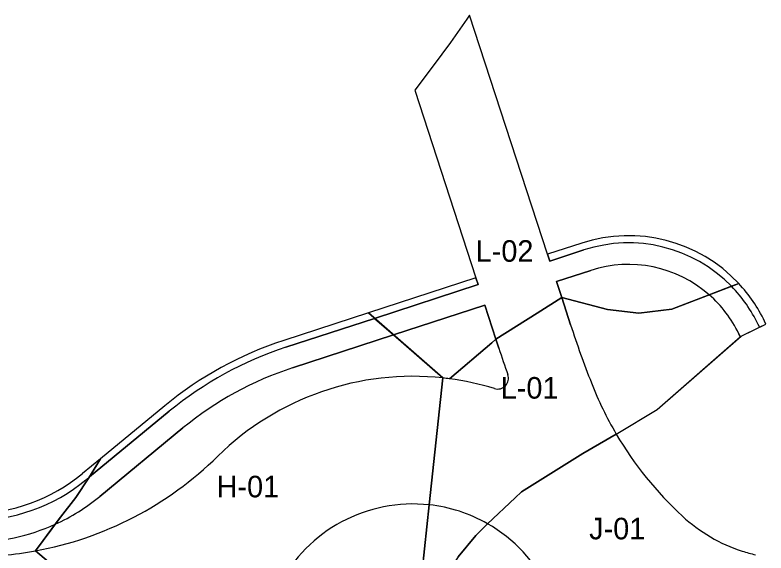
# Model space of a CAD drawing. Extents: x 5196716 to 5200291, y 3709146 to 3713154.
# Drawn here: x 5197340.6 to 5197549.6, y 3709372.1 to 3709521.7 of the extents above; entities that cross this region are included whole.
import ezdxf

# ---------------------------------------------------------------- set-up
doc = ezdxf.new("R2010")
doc.units = 0
for name, color, linetype in [('Drainage-Area', 7, 'Continuous'), ('dsnTextNote', 7, 'Continuous'), ('Level 1', 7, 'Continuous'), ('Level 2', 7, 'Continuous'), ('Level 4', 7, 'Continuous')]:
    doc.layers.add(name, color=color, linetype=linetype)

msp = doc.modelspace()

# ---------------------------------------------------------------- linework, layer by layer
at = {"layer": 'Drainage-Area'}
for points in [[(5197346.24, 3709372.65), (5197348.41, 3709375.52), (5197353.21, 3709382.02), (5197357.53, 3709387.5), (5197361.12, 3709392.93), (5197364.33, 3709398.3)], [(5197366.96, 3709358.52), (5197357.83, 3709363.71), (5197351.66, 3709368.11), (5197346.24, 3709372.65)]]:
    msp.add_lwpolyline(points, dxfattribs=at)
at = {"layer": 'Level 1'}
for p, q in [((5197488.79, 3709455.14), (5197467.07, 3709521.68)), ((5197451.81, 3709500.78), (5197468.83, 3709448.63)), ((5197498.3, 3709458.24), (5197488.79, 3709455.14)), ((5197498.3, 3709458.24), (5197488.79, 3709455.14)), ((5197468.83, 3709448.63), (5197438.91, 3709438.86)), ((5197438.91, 3709438.86), (5197415.36, 3709431.18)), ((5197459.67, 3709420.75), (5197438.91, 3709438.86)), ((5197438.91, 3709438.86), (5197459.67, 3709420.75)), ((5197542.62, 3709432.37), (5197549.57, 3709435.71)), ((5197549.57, 3709435.71), (5197549.18, 3709436.51)), ((5197549.57, 3709435.71), (5197549.18, 3709436.51)), ((5197519.27, 3709412.01), (5197542.62, 3709432.37)), ((5197455.86, 3709385.45), (5197459.67, 3709420.75)), ((5197459.67, 3709420.75), (5197455.86, 3709385.45)), ((5197382.24, 3709413.02), (5197364.33, 3709398.3)), ((5197507.89, 3709405.15), (5197519.27, 3709412.01)), ((5197498.6, 3709399.71), (5197507.89, 3709405.15)), ((5197498.6, 3709399.71), (5197507.89, 3709405.15)), ((5197507.89, 3709405.15), (5197498.6, 3709399.71)), ((5197481.5, 3709389.08), (5197498.6, 3709399.71)), ((5197498.6, 3709399.71), (5197481.5, 3709389.08)), ((5197481.5, 3709389.08), (5197498.6, 3709399.71)), ((5197498.6, 3709399.71), (5197481.5, 3709389.08)), ((5197364.33, 3709398.3), (5197359.35, 3709394.21)), ((5197479.8, 3709387.44), (5197481.5, 3709389.08)), ((5197481.5, 3709389.08), (5197479.8, 3709387.44)), ((5197479.8, 3709387.44), (5197481.5, 3709389.08)), ((5197481.5, 3709389.08), (5197479.8, 3709387.44)), ((5197472.07, 3709380.22), (5197479.8, 3709387.44)), ((5197479.8, 3709387.44), (5197472.07, 3709380.22)), ((5197472.07, 3709380.22), (5197479.8, 3709387.44)), ((5197479.8, 3709387.44), (5197472.07, 3709380.22)), ((5197451.32, 3709343.7), (5197455.86, 3709385.45)), ((5197455.86, 3709385.45), (5197451.32, 3709343.7))]:
    msp.add_line(p, q, dxfattribs=at)
for points in [[(5197467.07, 3709521.68), (5197466.31, 3709520.55), (5197461.73, 3709514.05), (5197456.99, 3709507.53), (5197451.81, 3709500.78)], [(5197541.97, 3709447.04), (5197523.39, 3709439.87), (5197514.18, 3709438.81), (5197505.42, 3709439.75), (5197492.72, 3709443.11)], [(5197492.72, 3709443.11), (5197505.42, 3709439.75), (5197514.18, 3709438.81), (5197523.39, 3709439.87), (5197541.97, 3709447.04)], [(5197492.72, 3709443.11), (5197485.88, 3709438.79), (5197474.4, 3709431.54)], [(5197474.4, 3709431.54), (5197485.88, 3709438.79), (5197492.72, 3709443.11)], [(5197474.4, 3709431.54), (5197473.26, 3709430.56), (5197461.53, 3709420.53)], [(5197461.53, 3709420.53), (5197473.26, 3709430.56), (5197474.4, 3709431.54)], [(5197346.24, 3709372.65), (5197348.41, 3709375.52), (5197353.21, 3709382.02), (5197357.53, 3709387.5), (5197361.12, 3709392.93), (5197364.33, 3709398.3)], [(5197364.33, 3709398.3), (5197361.12, 3709392.93), (5197357.53, 3709387.5), (5197353.21, 3709382.02), (5197348.41, 3709375.52), (5197346.24, 3709372.65)], [(5197472.07, 3709380.22), (5197468.83, 3709376.97), (5197463.95, 3709371), (5197459.45, 3709364.51), (5197455.96, 3709357.22), (5197452.99, 3709349.55), (5197451.32, 3709343.7)], [(5197463.95, 3709371), (5197468.83, 3709376.97), (5197472.07, 3709380.22)], [(5197472.07, 3709380.22), (5197468.83, 3709376.97), (5197463.95, 3709371)], [(5197366.96, 3709358.52), (5197357.83, 3709363.71), (5197351.66, 3709368.11), (5197346.24, 3709372.65)], [(5197346.24, 3709372.65), (5197351.66, 3709368.11), (5197357.83, 3709363.71), (5197366.96, 3709358.52)]]:
    msp.add_lwpolyline(points, dxfattribs=at)
for centre, radius, start, end in [((5197511.33, 3709418.32), 42, 43.1428, 108.0738), ((5197511.33, 3709418.32), 42, 25.6653, 43.1428), ((5197447, 3709334.21), 102, 108.0738, 129.4103), ((5197451.32, 3709343.7), 77.5, 82.4329, 83.8176), ((5197451.32, 3709343.7), 77.5, 82.4329, 83.8176), ((5197594.1, 3709455.83), 100, 210.4479, 227.3156), ((5197328.59, 3709431.06), 48, 269.8345, 309.8603), ((5197556.81, 3709415.4), 45, 227.3156, 252.0632), ((5197556.81, 3709415.4), 45, 252.0632, 256.9145)]:
    msp.add_arc(centre, radius, start, end, dxfattribs=at)
at = {"layer": 'Level 2'}
for p, q in [((5197488.79, 3709455.14), (5197467.07, 3709521.68)), ((5197451.81, 3709500.78), (5197468.83, 3709448.63)), ((5197498.92, 3709456.34), (5197489.41, 3709453.24)), ((5197489.41, 3709453.24), (5197488.79, 3709455.14)), ((5197491.27, 3709447.54), (5197500.78, 3709450.64)), ((5197468.83, 3709448.63), (5197469.45, 3709446.72)), ((5197492.72, 3709443.11), (5197491.27, 3709447.54)), ((5197469.45, 3709446.72), (5197440.66, 3709437.33)), ((5197539.95, 3709446.26), (5197533.76, 3709443.87)), ((5197533.76, 3709443.87), (5197539.95, 3709446.26)), ((5197495.2, 3709435.51), (5197492.72, 3709443.11)), ((5197445.93, 3709432.74), (5197471.31, 3709441.02)), ((5197471.31, 3709441.02), (5197474.4, 3709431.54)), ((5197440.66, 3709437.33), (5197415.98, 3709429.28)), ((5197440.66, 3709437.33), (5197445.93, 3709432.74)), ((5197445.93, 3709432.74), (5197440.66, 3709437.33)), ((5197547.76, 3709434.85), (5197547.38, 3709435.64)), ((5197541.97, 3709433.04), (5197542.39, 3709432.17)), ((5197542.62, 3709432.37), (5197547.76, 3709434.85)), ((5197417.84, 3709423.57), (5197445.93, 3709432.74)), ((5197474.4, 3709431.54), (5197475.23, 3709428.99)), ((5197542.39, 3709432.17), (5197542.62, 3709432.37)), ((5197459.67, 3709420.75), (5197455.86, 3709385.45)), ((5197455.86, 3709385.45), (5197459.67, 3709420.75)), ((5197383.51, 3709411.47), (5197361.29, 3709393.21)), ((5197364.15, 3709387.79), (5197387.32, 3709406.84)), ((5197507.89, 3709405.15), (5197498.6, 3709399.71)), ((5197498.6, 3709399.71), (5197507.89, 3709405.15)), ((5197498.6, 3709399.71), (5197481.5, 3709389.08)), ((5197481.5, 3709389.08), (5197498.6, 3709399.71)), ((5197361.29, 3709393.21), (5197360.34, 3709392.42)), ((5197361.29, 3709393.21), (5197361.12, 3709392.93)), ((5197361.12, 3709392.93), (5197361.29, 3709393.21)), ((5197361.12, 3709392.93), (5197357.53, 3709387.5)), ((5197357.53, 3709387.5), (5197361.12, 3709392.93)), ((5197481.5, 3709389.08), (5197479.8, 3709387.44)), ((5197479.8, 3709387.44), (5197481.5, 3709389.08)), ((5197357.53, 3709387.5), (5197353.21, 3709382.02)), ((5197353.21, 3709382.02), (5197357.53, 3709387.5)), ((5197479.8, 3709387.44), (5197472.07, 3709380.22)), ((5197472.07, 3709380.22), (5197479.8, 3709387.44)), ((5197353.21, 3709382.02), (5197351.78, 3709380.08)), ((5197351.78, 3709380.08), (5197353.21, 3709382.02)), ((5197351.66, 3709368.11), (5197346.24, 3709372.65))]:
    msp.add_line(p, q, dxfattribs=at)
for points in [[(5197467.07, 3709521.68), (5197466.31, 3709520.55), (5197461.73, 3709514.05), (5197456.99, 3709507.53), (5197451.81, 3709500.78)], [(5197492.72, 3709443.11), (5197485.88, 3709438.79), (5197474.4, 3709431.54)], [(5197474.4, 3709431.54), (5197485.88, 3709438.79), (5197492.72, 3709443.11)], [(5197346.24, 3709372.65), (5197351.66, 3709368.11), (5197357.83, 3709363.71), (5197366.96, 3709358.52)]]:
    msp.add_lwpolyline(points, dxfattribs=at)
for centre, radius, start, end in [((5197511.33, 3709418.32), 40, 44.3081, 108.0738), ((5197511.33, 3709418.32), 34, 48.7225, 108.0738), ((5197511.33, 3709418.32), 40, 25.6653, 44.3081), ((5197511.33, 3709418.32), 34, 25.6653, 48.7225), ((5197778.02, 3709527.81), 297.5, 198.0738, 201.3741), ((5197447, 3709334.21), 100, 108.0738, 129.4106), ((5197778.02, 3709527.81), 318.5, 198.0738, 199.4651), ((5197447, 3709334.21), 94, 108.0738, 129.4106), ((5197451.32, 3709343.7), 77.5, 83.8176, 134.4832), ((5197451.32, 3709343.7), 77.5, 82.4329, 83.8176), ((5197451.32, 3709343.7), 77.5, 72.9739, 82.4329), ((5197474.89, 3709420.67), 3, 252.9739, 19.4651), ((5197594.1, 3709455.83), 100, 201.3741, 210.4479), ((5197594.1, 3709455.83), 100, 210.4479, 227.3156), ((5197328.7, 3709468.56), 97.5, 280.3656, 314.4832), ((5197328.59, 3709431.06), 50, 269.8345, 309.4106), ((5197328.59, 3709431.06), 56, 294.4582, 309.4106), ((5197451.32, 3709343.7), 42, 83.8009, 152.6258), ((5197451.32, 3709343.7), 42, 60.3941, 83.8011), ((5197556.81, 3709415.4), 45, 227.3156, 252.0632), ((5197328.59, 3709431.06), 56, 269.8345, 294.4582), ((5197451.32, 3709343.7), 42, 25.7605, 60.3941), ((5197328.7, 3709468.56), 97.5, 269.8354, 280.3656), ((5197556.81, 3709415.4), 45, 252.0632, 256.9145)]:
    msp.add_arc(centre, radius, start, end, dxfattribs=at)
at = {"layer": 'Level 4'}
for p, q in [((5197498.3, 3709458.24), (5197488.79, 3709455.14)), ((5197489.41, 3709453.24), (5197498.92, 3709456.34)), ((5197488.79, 3709455.14), (5197489.41, 3709453.24)), ((5197500.78, 3709450.64), (5197491.27, 3709447.54)), ((5197468.83, 3709448.63), (5197438.91, 3709438.86)), ((5197469.45, 3709446.72), (5197468.83, 3709448.63)), ((5197491.27, 3709447.54), (5197492.72, 3709443.11)), ((5197440.66, 3709437.33), (5197469.45, 3709446.72)), ((5197539.95, 3709446.26), (5197541.97, 3709447.04)), ((5197541.97, 3709447.04), (5197539.95, 3709446.26)), ((5197492.72, 3709443.11), (5197505.42, 3709439.75)), ((5197505.42, 3709439.75), (5197492.72, 3709443.11)), ((5197492.72, 3709443.11), (5197495.2, 3709435.51)), ((5197471.31, 3709441.02), (5197445.93, 3709432.74)), ((5197474.4, 3709431.54), (5197471.31, 3709441.02)), ((5197514.18, 3709438.81), (5197505.42, 3709439.75)), ((5197438.91, 3709438.86), (5197415.36, 3709431.18)), ((5197415.98, 3709429.28), (5197440.66, 3709437.33)), ((5197438.91, 3709438.86), (5197440.66, 3709437.33)), ((5197440.66, 3709437.33), (5197438.91, 3709438.86)), ((5197547.38, 3709435.64), (5197547.76, 3709434.85)), ((5197547.76, 3709434.85), (5197549.57, 3709435.71)), ((5197549.57, 3709435.71), (5197549.18, 3709436.51)), ((5197542.39, 3709432.17), (5197541.97, 3709433.04)), ((5197445.93, 3709432.74), (5197417.84, 3709423.57)), ((5197445.93, 3709432.74), (5197459.67, 3709420.75)), ((5197459.67, 3709420.75), (5197445.93, 3709432.74)), ((5197473.26, 3709430.56), (5197474.4, 3709431.54)), ((5197475.23, 3709428.99), (5197474.4, 3709431.54)), ((5197519.27, 3709412.01), (5197542.39, 3709432.17)), ((5197461.53, 3709420.53), (5197473.26, 3709430.56)), ((5197382.24, 3709413.02), (5197364.33, 3709398.3)), ((5197507.89, 3709405.15), (5197519.27, 3709412.01)), ((5197361.29, 3709393.21), (5197383.51, 3709411.47)), ((5197387.32, 3709406.84), (5197364.15, 3709387.79)), ((5197364.33, 3709398.3), (5197359.35, 3709394.21)), ((5197364.33, 3709398.3), (5197361.29, 3709393.21)), ((5197361.29, 3709393.21), (5197364.33, 3709398.3)), ((5197360.34, 3709392.42), (5197361.29, 3709393.21)), ((5197455.86, 3709385.45), (5197451.32, 3709343.7)), ((5197451.32, 3709343.7), (5197455.86, 3709385.45)), ((5197348.41, 3709375.52), (5197351.78, 3709380.08)), ((5197346.24, 3709372.65), (5197348.41, 3709375.52))]:
    msp.add_line(p, q, dxfattribs=at)
for points in [[(5197505.42, 3709439.75), (5197514.18, 3709438.81), (5197523.39, 3709439.87), (5197533.76, 3709443.87)], [(5197533.76, 3709443.87), (5197523.39, 3709439.87), (5197514.18, 3709438.81)], [(5197474.4, 3709431.54), (5197473.26, 3709430.56), (5197461.53, 3709420.53)], [(5197351.78, 3709380.08), (5197348.41, 3709375.52), (5197346.24, 3709372.65)], [(5197472.07, 3709380.22), (5197468.83, 3709376.97), (5197463.95, 3709371)], [(5197463.95, 3709371), (5197468.83, 3709376.97), (5197472.07, 3709380.22)]]:
    msp.add_lwpolyline(points, dxfattribs=at)
for centre, radius, start, end in [((5197511.33, 3709418.32), 42, 43.1428, 108.0738), ((5197511.33, 3709418.32), 40, 44.3081, 108.0738), ((5197511.33, 3709418.32), 34, 48.7225, 108.0738), ((5197511.33, 3709418.32), 40, 25.6653, 44.3081), ((5197511.33, 3709418.32), 42, 25.6653, 43.1428), ((5197511.33, 3709418.32), 34, 25.6653, 48.7225), ((5197778.02, 3709527.81), 297.5, 198.0738, 201.3741), ((5197447, 3709334.21), 102, 108.0738, 129.4103), ((5197447, 3709334.21), 100, 108.0738, 129.4106), ((5197778.02, 3709527.81), 318.5, 198.0738, 199.4651), ((5197447, 3709334.21), 94, 108.0738, 129.4106), ((5197451.32, 3709343.7), 77.5, 83.8176, 134.4832), ((5197451.32, 3709343.7), 77.5, 82.4329, 83.8176), ((5197451.32, 3709343.7), 77.5, 72.9739, 82.4329), ((5197474.89, 3709420.67), 3, 252.9739, 19.4651), ((5197594.1, 3709455.83), 100, 201.3741, 210.4479), ((5197328.7, 3709468.56), 97.5, 280.3656, 314.4832), ((5197328.59, 3709431.06), 48, 269.8345, 309.8603), ((5197328.59, 3709431.06), 50, 269.8345, 309.4106), ((5197328.59, 3709431.06), 56, 294.4582, 309.4106), ((5197451.32, 3709343.7), 42, 83.8009, 152.6258), ((5197451.32, 3709343.7), 42, 60.3941, 83.8011), ((5197328.59, 3709431.06), 56, 269.8345, 294.4582), ((5197451.32, 3709343.7), 42, 25.7605, 60.3941), ((5197328.7, 3709468.56), 97.5, 269.8354, 280.3656)]:
    msp.add_arc(centre, radius, start, end, dxfattribs=at)

# ---------------------------------------------------------------- texts
at = {"layer": 'dsnTextNote'}
for s, p in [('L-02', (5197468.79, 3709453.06)), ('L-01', (5197475.76, 3709415)), ('H-01', (5197396.69, 3709387.54)), ('J-01', (5197500.36, 3709375.86))]:
    msp.add_text(s, height=6, dxfattribs=at).set_placement(p)

doc.saveas('drawing.dxf')
